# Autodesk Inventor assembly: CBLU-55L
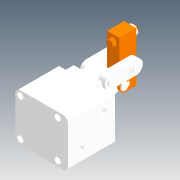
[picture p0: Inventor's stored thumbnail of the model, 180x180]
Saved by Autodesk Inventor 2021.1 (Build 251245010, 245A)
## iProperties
Created: 2019-05
Part Number: CBLU-55L
Description: STEP AP214
Document SubType Name: Assembly
Designer: user
Title: CBLU-55L.STEP
Revision Number: ÈÎºÎ
Sending System: SolidWorks 2016
Preprocessor: SwSTEP 2.0
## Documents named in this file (11)
- D:\Vault_2016\Projekty\Clamptek\Hydraulic\CBLU\CBLU-55\Inventor\CBLU-55L\CBLU-55L.iam
- D:\Vault_2016\Projekty\Clamptek\Hydraulic\CBLU\CBLU-55\Inventor\CBLU-55L\CBLU-55CL±¾Ìå_1_1_1.ipt
- D:\Vault_2016\Projekty\Clamptek\Hydraulic\CBLU\CBLU-55\Inventor\CBLU-55L\changxiao.ipt
- D:\Vault_2016\Projekty\Clamptek\Hydraulic\CBLU\CBLU-55\Inventor\CBLU-55L\duanxiao.ipt
- D:\Vault_2016\Projekty\Clamptek\Hydraulic\CBLU\CBLU-55\Inventor\CBLU-55L\huosaigan_3_1.ipt
- D:\Vault_2016\Projekty\Clamptek\Hydraulic\CBLU\CBLU-55\Inventor\CBLU-55L\kahuang.ipt
- D:\Vault_2016\Projekty\Clamptek\Hydraulic\CBLU\CBLU-55\Inventor\CBLU-55L\kahuang01.ipt
- D:\Vault_2016\Projekty\Clamptek\Hydraulic\CBLU\CBLU-55\Inventor\CBLU-55L\liangan.ipt
- D:\Vault_2016\Projekty\Clamptek\Hydraulic\CBLU\CBLU-55\Inventor\CBLU-55L\luogan.ipt
- D:\Vault_2016\Projekty\Clamptek\Hydraulic\CBLU\CBLU-55\Inventor\CBLU-55L\luomu.ipt
- D:\Vault_2016\Projekty\Clamptek\Hydraulic\CBLU\CBLU-55\Inventor\CBLU-55L\yabi.ipt
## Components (16 placed, 16 different names)
1. CBLU-55CL±¾Ìå_1_1_1_1
2. changxiao_2
3. duanxiao_3
4. huosaigan_3_1_4
5. kahuang_5
6. kahuang01_6
7. liangan_7
8. luogan_8
9. luomu_9
10. yabi_10
11. liangan_11
12. kahuang01_12
13. changxiao_13
14. kahuang_14
15. kahuang_15
16. kahuang_16
